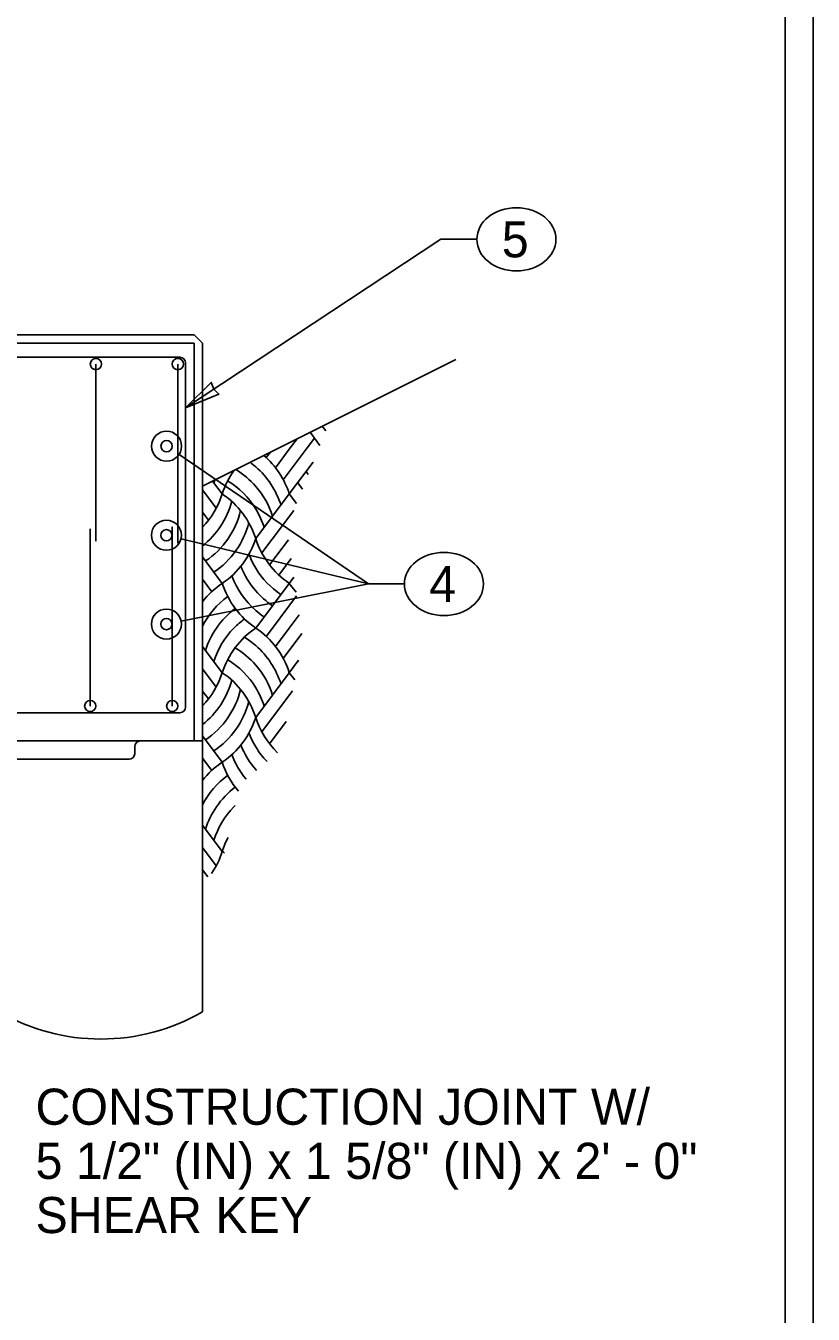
# Model space of a CAD drawing. Extents: x 99888 to 103177, y 100000 to 102076.
# Drawn here: x 102801 to 103150, y 100934 to 101505 of the extents above; entities that cross this region are included whole.
import ezdxf

# ---------------------------------------------------------------- set-up
doc = ezdxf.new("R2010")
doc.units = 0
for name, color, linetype in [('Level 10', 7, 'Continuous'), ('Level 15', 7, 'Continuous'), ('Level 2', 7, 'Continuous'), ('Level 20', 7, 'Continuous'), ('Level 36', 7, 'Continuous'), ('SH_GI_PlotLimits', 7, 'Continuous'), ('SH_GI_SheetBorder', 7, 'Continuous')]:
    doc.layers.add(name, color=color, linetype=linetype)

msp = doc.modelspace()

# ---------------------------------------------------------------- linework, layer by layer
at = {"layer": 'Level 10'}
for p, q in [((102709.45, 101358.23), (102869.45, 101358.23)), ((102832.24, 101355.23), (102832.24, 101276.75)), ((102832.24, 101355.23), (102832.24, 101276.75)), ((102868.54, 101355.23), (102868.54, 101275.85)), ((102868.54, 101355.23), (102868.54, 101275.85)), ((102871.95, 101355.73), (102871.95, 101203.23)), ((102829.74, 101203.73), (102829.74, 101282.21)), ((102866.04, 101203.73), (102866.04, 101283.11)), ((102866.04, 101203.73), (102866.04, 101283.11)), ((102869.45, 101200.73), (102709.45, 101200.73))]:
    msp.add_line(p, q, dxfattribs=at)
for centre in [(102863.54, 101318.86), (102863.54, 101318.86), (102863.49, 101279.39), (102863.49, 101279.39), (102863.49, 101240.02), (102863.49, 101240.02), (102829.74, 101203.73), (102829.74, 101203.73), (102866.04, 101203.73), (102866.04, 101203.73)]:
    msp.add_circle(centre, 2.5, dxfattribs=at)
for centre, start, end in [((102869.45, 101355.73), 0, 90), ((102869.45, 101203.23), 270, 0)]:
    msp.add_arc(centre, 2.5, start, end, dxfattribs=at)
at = {"layer": 'Level 15'}
for p, q in [((102871.95, 101335.82), (102985.01, 101410.51)), ((102871.95, 101335.82), (102985.01, 101410.51)), ((103001.01, 101410.51), (102985.01, 101410.51)), ((103001.01, 101410.51), (102985.01, 101410.51)), ((102879.45, 101301.15), (102991.61, 101357.23)), ((102932.53, 101327.69), (102934.08, 101325.61)), ((102932.53, 101327.69), (102934.08, 101325.61)), ((102917.91, 101317.48), (102921.39, 101322.12)), ((102917.91, 101317.48), (102921.39, 101322.12)), ((102925.33, 101317.48), (102929.05, 101322.43)), ((102925.33, 101317.48), (102929.05, 101322.43)), ((102927.13, 101324.99), (102931.49, 101319.17)), ((102927.13, 101324.99), (102931.49, 101319.17)), ((102952.92, 101257.8), (102869.05, 101315.1)), ((102952.92, 101257.8), (102869.05, 101315.1)), ((102907.71, 101313.78), (102909.51, 101316.18)), ((102907.71, 101313.78), (102909.51, 101316.18)), ((102911.79, 101309.32), (102917.91, 101317.48)), ((102911.79, 101309.32), (102917.91, 101317.48)), ((102915.23, 101304.01), (102925.33, 101317.48)), ((102915.23, 101304.01), (102925.33, 101317.48)), ((102917.91, 101297.68), (102928.53, 101311.83)), ((102917.91, 101297.68), (102928.53, 101311.83)), ((102883.93, 101303.39), (102888.21, 101297.68)), ((102883.93, 101303.39), (102888.21, 101297.68)), ((102921.62, 101302.63), (102923.69, 101299.86)), ((102921.62, 101302.63), (102923.69, 101299.86)), ((102925.33, 101307.58), (102926.29, 101306.3)), ((102925.33, 101307.58), (102926.29, 101306.3)), ((102879.45, 101299.46), (102885.54, 101291.34)), ((102879.45, 101299.46), (102885.54, 101291.34)), ((102903.06, 101277.88), (102917.91, 101297.68)), ((102903.06, 101277.88), (102917.91, 101297.68)), ((102917.91, 101297.68), (102921.1, 101293.43)), ((102917.91, 101297.68), (102921.1, 101293.43)), ((102879.45, 101289.56), (102882.09, 101286.03)), ((102879.45, 101289.56), (102882.09, 101286.03)), ((102905.73, 101271.54), (102919.88, 101290.4)), ((102905.73, 101271.54), (102919.88, 101290.4)), ((102952.92, 101257.8), (102869.97, 101277.83)), ((102952.92, 101257.8), (102869.97, 101277.83)), ((102909.18, 101266.24), (102917.55, 101277.41)), ((102909.18, 101266.24), (102917.55, 101277.41)), ((102879.45, 101269.76), (102888.21, 101258.08)), ((102879.45, 101269.76), (102888.21, 101258.08)), ((102913.25, 101261.77), (102918.75, 101269.09)), ((102913.25, 101261.77), (102918.75, 101269.09)), ((102952.92, 101257.8), (102870.03, 101241.32)), ((102952.92, 101257.8), (102870.03, 101241.32)), ((102879.45, 101259.86), (102883.56, 101254.38)), ((102879.45, 101259.86), (102883.56, 101254.38)), ((102903.06, 101238.28), (102917.91, 101258.08)), ((102903.06, 101238.28), (102917.91, 101258.08)), ((102917.91, 101258.08), (102919.94, 101260.78)), ((102917.91, 101258.08), (102919.94, 101260.78)), ((102917.91, 101258.08), (102920.89, 101254.1)), ((102917.91, 101258.08), (102920.89, 101254.1)), ((102968.92, 101257.8), (102952.92, 101257.8)), ((102968.92, 101257.8), (102952.92, 101257.8)), ((102910.48, 101238.28), (102921.13, 101252.47)), ((102910.48, 101238.28), (102921.13, 101252.47)), ((102917.91, 101238.28), (102922.32, 101244.16)), ((102917.91, 101238.28), (102922.32, 101244.16)), ((102907.71, 101234.59), (102910.48, 101238.28)), ((102907.71, 101234.59), (102910.48, 101238.28)), ((102911.79, 101230.12), (102917.91, 101238.28)), ((102911.79, 101230.12), (102917.91, 101238.28)), ((102915.23, 101224.81), (102923.51, 101235.85)), ((102915.23, 101224.81), (102923.51, 101235.85)), ((102879.45, 101230.16), (102888.21, 101218.48)), ((102879.45, 101230.16), (102888.21, 101218.48)), ((102917.91, 101218.48), (102922.04, 101223.98)), ((102917.91, 101218.48), (102922.04, 101223.98)), ((102921.62, 101223.43), (102921.86, 101223.11)), ((102921.62, 101223.43), (102921.86, 101223.11)), ((102879.45, 101220.26), (102885.54, 101212.15)), ((102879.45, 101220.26), (102885.54, 101212.15)), ((102903.06, 101198.68), (102917.91, 101218.48)), ((102903.06, 101198.68), (102917.91, 101218.48)), ((102917.91, 101218.48), (102920.29, 101215.31)), ((102917.91, 101218.48), (102920.29, 101215.31)), ((102879.45, 101210.36), (102882.09, 101206.84)), ((102879.45, 101210.36), (102882.09, 101206.84)), ((102905.73, 101192.35), (102919.3, 101210.44)), ((102905.73, 101192.35), (102919.3, 101210.44)), ((102909.18, 101187.04), (102916.57, 101196.89)), ((102909.18, 101187.04), (102916.57, 101196.89)), ((102879.45, 101190.56), (102888.21, 101178.88)), ((102879.45, 101190.56), (102888.21, 101178.88)), ((102879.45, 101180.66), (102883.56, 101175.19)), ((102879.45, 101180.66), (102883.56, 101175.19)), ((102879.45, 101170.76), (102879.48, 101170.73)), ((102879.45, 101170.76), (102879.48, 101170.73)), ((102879.45, 101150.96), (102888.21, 101139.28)), ((102879.45, 101150.96), (102888.21, 101139.28)), ((102879.45, 101141.06), (102885.54, 101132.95)), ((102879.45, 101141.06), (102885.54, 101132.95)), ((102879.45, 101131.16), (102881.82, 101128)), ((102879.45, 101131.16), (102881.82, 101128))]:
    msp.add_line(p, q, dxfattribs=at)
msp.add_lwpolyline([(102871.95, 101335.82), (102886.76, 101341.93), (102884.45, 101344.1), (102883.36, 101347.07)], close=True, dxfattribs=at)
for centre in [(102863.54, 101318.86), (102863.54, 101318.86), (102863.49, 101279.39), (102863.49, 101279.39), (102863.49, 101240.02), (102863.49, 101240.02)]:
    msp.add_circle(centre, 6.67, dxfattribs=at)
for centre, start, end in [((102882.1, 101286.29), 17.6434, 49.2232), ((102882.1, 101286.29), 17.6434, 49.2232), ((102924.02, 101286.29), 144.4175, 162.3566), ((102924.02, 101286.29), 144.4175, 162.3566), ((102874.68, 101276.39), 40.9413, 58.7405), ((102874.68, 101276.39), 40.9413, 58.7405), ((102878.39, 101281.34), 48.9597, 53.8798), ((102878.39, 101281.34), 48.9597, 53.8798), ((102878.39, 101281.34), 17.6434, 48.9597), ((102878.39, 101281.34), 17.6434, 48.9597), ((102920.31, 101291.24), 160.3321, 162.3566), ((102920.31, 101291.24), 160.3321, 162.3566), ((102870.96, 101271.44), 31.3316, 58.4874), ((102870.96, 101271.44), 31.3316, 58.4874), ((102852.4, 101309.07), 316.0437, 342.3566), ((102852.4, 101309.07), 316.0437, 342.3566), ((102867.25, 101266.49), 17.6434, 56.0964), ((102867.25, 101266.49), 17.6434, 56.0964), ((102874.67, 101276.39), 17.6434, 40.9414), ((102874.67, 101276.39), 17.6434, 40.9414), ((102856.11, 101304.12), 308.3949, 345.0113), ((102856.11, 101304.12), 308.3949, 345.0113), ((102870.96, 101271.44), 17.6434, 31.3317), ((102870.96, 101271.44), 17.6434, 31.3317), ((102859.83, 101299.17), 303.9036, 346.3199), ((102859.83, 101299.17), 303.9036, 346.3199), ((102863.54, 101294.22), 303.9036, 345.7713), ((102863.54, 101294.22), 303.9036, 345.7713), ((102867.25, 101289.27), 303.9036, 342.3566), ((102867.25, 101289.27), 303.9036, 342.3566), ((102938.87, 101289.27), 197.6435, 236.0964), ((102938.87, 101289.27), 197.6435, 236.0964), ((102935.16, 101284.32), 200.8778, 211.332), ((102935.16, 101284.32), 200.8778, 211.332), ((102931.45, 101279.37), 201.4344, 220.9416), ((102931.45, 101279.37), 201.4344, 220.9416), ((102935.16, 101284.32), 211.3319, 236.0964), ((102935.16, 101284.32), 211.3319, 236.0964), ((102909.17, 101226.89), 123.9036, 142.2687), ((102909.17, 101226.89), 123.9036, 142.2687), ((102924.02, 101269.47), 197.6434, 236.0964), ((102924.02, 101269.47), 197.6434, 236.0964), ((102927.73, 101274.42), 200.2432, 228.9599), ((102927.73, 101274.42), 200.2432, 228.9599), ((102912.88, 101221.94), 126.3063, 152.8331), ((102912.88, 101221.94), 126.3063, 152.8331), ((102931.44, 101279.37), 220.9415, 236.0964), ((102931.44, 101279.37), 220.9415, 236.0964), ((102916.6, 101216.99), 127.1006, 145.4911), ((102916.6, 101216.99), 127.1006, 145.4911), ((102927.73, 101274.42), 228.9599, 236.0964), ((102927.73, 101274.42), 228.9599, 236.0964), ((102920.31, 101212.04), 126.331, 135.7128), ((102920.31, 101212.04), 126.331, 135.7128), ((102916.6, 101216.99), 145.491, 162.3566), ((102916.6, 101216.99), 145.491, 162.3566), ((102920.31, 101212.04), 135.7127, 162.3566), ((102920.31, 101212.04), 135.7127, 162.3566), ((102924.02, 101207.09), 123.9036, 162.3566), ((102924.02, 101207.09), 123.9036, 162.3566), ((102878.39, 101202.14), 48.9597, 58.5465), ((102878.39, 101202.14), 48.9597, 58.5465), ((102882.1, 101207.09), 17.6434, 56.0963), ((102882.1, 101207.09), 17.6434, 56.0963), ((102874.68, 101197.19), 40.9413, 59.3021), ((102874.68, 101197.19), 40.9413, 59.3021), ((102878.39, 101202.14), 17.6434, 48.9597), ((102878.39, 101202.14), 17.6434, 48.9597), ((102870.96, 101192.24), 31.3316, 58.4874), ((102870.96, 101192.24), 31.3316, 58.4874), ((102852.4, 101229.87), 316.0437, 342.3566), ((102852.4, 101229.87), 316.0437, 342.3566), ((102867.25, 101187.29), 17.6434, 56.0964), ((102867.25, 101187.29), 17.6434, 56.0964), ((102874.67, 101197.19), 17.6434, 40.9414), ((102874.67, 101197.19), 17.6434, 40.9414), ((102856.11, 101224.92), 308.3949, 345.0113), ((102856.11, 101224.92), 308.3949, 345.0113), ((102859.83, 101219.97), 303.9036, 346.3199), ((102859.83, 101219.97), 303.9036, 346.3199), ((102870.96, 101192.24), 17.6434, 31.3317), ((102870.96, 101192.24), 17.6434, 31.3317), ((102863.54, 101215.02), 303.9036, 345.7713), ((102863.54, 101215.02), 303.9036, 345.7713), ((102867.25, 101210.07), 303.9036, 342.3566), ((102867.25, 101210.07), 303.9036, 342.3566), ((102938.87, 101210.07), 197.6435, 225.9663), ((102938.87, 101210.07), 197.6435, 225.9663), ((102935.16, 101205.12), 200.8778, 211.332), ((102935.16, 101205.12), 200.8778, 211.332), ((102931.45, 101200.17), 201.4344, 220.9416), ((102931.45, 101200.17), 201.4344, 220.9416), ((102935.16, 101205.12), 211.3319, 223.8046), ((102935.16, 101205.12), 211.3319, 223.8046), ((102909.17, 101147.69), 123.9036, 142.2687), ((102909.17, 101147.69), 123.9036, 142.2687), ((102924.02, 101190.27), 197.6434, 220.3148), ((102924.02, 101190.27), 197.6434, 220.3148), ((102927.73, 101195.22), 200.2432, 219.4936), ((102927.73, 101195.22), 200.2432, 219.4936), ((102912.88, 101142.74), 126.3063, 152.8331), ((102912.88, 101142.74), 126.3063, 152.8331), ((102931.44, 101200.17), 220.9415, 221.6483), ((102931.44, 101200.17), 220.9415, 221.6483), ((102916.6, 101137.79), 127.1006, 145.4911), ((102916.6, 101137.79), 127.1006, 145.4911), ((102916.6, 101137.79), 145.491, 162.3566), ((102916.6, 101137.79), 145.491, 162.3566), ((102920.31, 101132.85), 135.7127, 162.3566), ((102920.31, 101132.85), 135.7127, 162.3566), ((102920.31, 101132.85), 134.5137, 135.7128), ((102920.31, 101132.85), 134.5137, 135.7128), ((102924.02, 101127.9), 152.0696, 162.3566), ((102924.02, 101127.9), 152.0696, 162.3566), ((102870.96, 101113.05), 58.2914, 58.4874), ((102870.96, 101113.05), 58.2914, 58.4874), ((102852.4, 101150.67), 325.8649, 342.3566), ((102852.4, 101150.67), 325.8649, 342.3566), ((102867.25, 101108.1), 54.118, 56.0964), ((102867.25, 101108.1), 54.118, 56.0964)]:
    msp.add_arc(centre, 37.58, start, end, dxfattribs=at)
at = {"layer": 'Level 2'}
for p, q in [((102875.7, 101368.23), (102703.2, 101368.23)), ((102875.7, 101368.23), (102879.45, 101364.48)), ((102875.7, 101368.23), (102879.45, 101364.48)), ((102703.2, 101364.48), (102875.7, 101364.48)), ((102703.2, 101364.48), (102875.7, 101364.48)), ((102875.7, 101364.48), (102875.7, 101188.23)), ((102875.7, 101364.48), (102875.7, 101188.23)), ((102879.45, 101364.48), (102879.45, 101188.23)), ((102879.45, 101068.23), (102879.45, 101188.23))]:
    msp.add_line(p, q, dxfattribs=at)
msp.add_arc((102834.45, 101146.17), 90, 240, 300, dxfattribs=at)
at = {"layer": 'Level 20'}
for centre in [(103018.51, 101410.51), (102986.42, 101257.8)]:
    msp.add_ellipse(centre, major_axis=(-17.5, 0), ratio=0.8, dxfattribs=at)
at = {"layer": 'Level 36'}
for p, q in [((102699.45, 101188.23), (102879.45, 101188.23)), ((102849.45, 101182.61), (102849.45, 101185.73)), ((102731.95, 101180.11), (102846.95, 101180.11))]:
    msp.add_line(p, q, dxfattribs=at)
for centre in [(102832.24, 101355.23), (102832.24, 101355.23), (102868.54, 101355.23), (102868.54, 101355.23)]:
    msp.add_circle(centre, 2.5, dxfattribs=at)
for centre, start, end in [((102851.95, 101185.73), 90, 180), ((102846.95, 101182.61), 270, 0)]:
    msp.add_arc(centre, 2.5, start, end, dxfattribs=at)
at = {"layer": 'SH_GI_PlotLimits'}
msp.add_lwpolyline([(99888.5, 100000), (103150, 100000), (103150, 102075.5), (99888.5, 102075.5)], close=True, dxfattribs=at)
msp.add_lwpolyline([(99888.5, 100000), (103150, 100000), (103150, 102075.5), (99888.5, 102075.5)], close=True, dxfattribs=at)
at = {"layer": 'SH_GI_SheetBorder'}
msp.add_line((103137.64, 102063.15), (103137.64, 100012.35), dxfattribs=at)
msp.add_line((103137.64, 102063.15), (103137.64, 100012.35), dxfattribs=at)

# ---------------------------------------------------------------- texts
at = {"layer": 'Level 20'}
for s, p in [('5', (103012.05, 101402.51)), ('4', (102979.91, 101249.81))]:
    msp.add_text(s, height=16, dxfattribs=at).set_placement(p)
for s, p in [('CONSTRUCTION JOINT W/', (102805.5, 101018.19)), ('5 1/2" (IN) x 1 5/8" (IN) x 2\' - 0"', (102805.5, 100994.19)), ('SHEAR KEY', (102805.5, 100970.19))]:
    msp.add_text(s, height=16, rotation=360, dxfattribs=at).set_placement(p)

doc.saveas('drawing.dxf')
